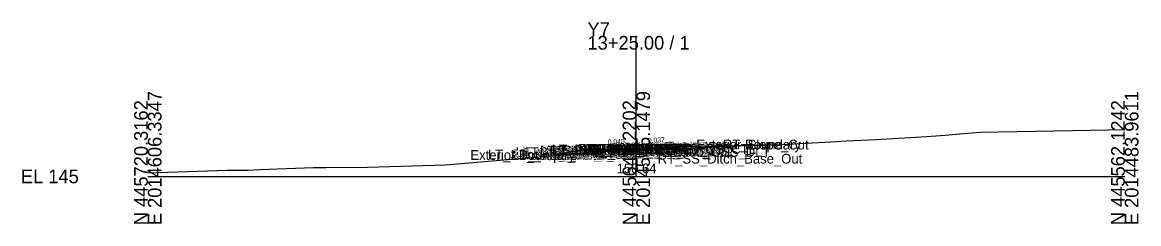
# Model space of a CAD drawing. Extents: x -26 to 203, y -10 to 7527.
# Drawn here: x -25.7 to 202.8, y 6490.3 to 6531.6 of the extents above; entities that cross this region are included whole.
import ezdxf

# ---------------------------------------------------------------- set-up
doc = ezdxf.new("R2010")
doc.units = 0
for name, color, linetype in [('Exist CMT Pavement', 7, 'Continuous'), ('Exist Cross Section Cell', 7, 'Continuous'), ('Exist XS Center Line Elevation Label', 7, 'Continuous'), ('Exist XS Ground Line', 7, 'Continuous'), ('Prop CMT Pvmt Course 1', 7, 'Continuous'), ('Prop CMT Pvmt Course 1 Wedge', 7, 'Continuous'), ('Prop CMT Pvmt Course 2', 7, 'Continuous'), ('Prop CMT Pvmt Course 2 Wedge', 7, 'Continuous'), ('Prop CMT Pvmt Course 3', 7, 'Continuous'), ('Prop CMT Pvmt Course 3 Wedge', 7, 'Continuous'), ('Prop CMT Pvmt Surface', 7, 'Continuous'), ('Prop CMT Pvmt Surface Shoulder', 7, 'Continuous'), ('Prop CMT Pvmt Wedge Surface 1', 7, 'Continuous'), ('Prop CMT Pvmt Wedge Surface 2', 7, 'Continuous'), ('Prop CMT Pvmt Wedge Surface 3', 7, 'Continuous'), ('Prop CMT Shld Paved Course 1', 7, 'Continuous'), ('Prop CMT Shld Paved Course 2', 7, 'Continuous'), ('Prop CMT Shld Paved Course 3', 7, 'Continuous'), ('Prop CMT Slope Grass', 7, 'Continuous'), ('Prop CMT Subgrade Earthwork', 7, 'Continuous'), ('Prop XS Earthwork Shape', 7, 'Continuous'), ('Prop XS SE Text', 7, 'Continuous'), ('Prop XS Side Slope Text', 7, 'Continuous'), ('Scratch_Level_0', 7, 'Continuous')]:
    doc.layers.add(name, color=color, linetype=linetype)

msp = doc.modelspace()

# ---------------------------------------------------------------- linework, layer by layer
at = {"layer": 'Exist CMT Pavement'}
msp.add_lwpolyline([(92.94, 6505.28), (96.94, 6505.54), (99.25, 6505.64), (100, 6505.64), (105.97, 6505.67), (107.36, 6505.68)], dxfattribs=at)
at = {"layer": 'Exist Cross Section Cell'}
for p, q in [((100, 6500), (100, 6528.78)), ((0, 6500), (100, 6500)), ((100, 6500), (200, 6500))]:
    msp.add_line(p, q, dxfattribs=at)
at = {"layer": 'Exist XS Ground Line'}
msp.add_lwpolyline([(0, 6500.76), (16.3, 6501.28), (20.4, 6501.31), (22.93, 6501.4), (33.83, 6501.79), (36.47, 6501.83), (44.97, 6501.9), (60.97, 6502.39), (87.21, 6504.6), (90.59, 6504.96), (90.9, 6505.08), (91.34, 6505.18), (96.94, 6505.54), (99.25, 6505.64), (100, 6505.64), (105.97, 6505.67), (108.19, 6505.68), (108.48, 6506.01), (108.95, 6505.67), (111.52, 6505.8), (120.48, 6506.25), (126.7, 6506.43), (127.61, 6506.46), (128.31, 6506.49), (134.74, 6506.84), (140.96, 6507.16), (141.87, 6507.2), (143.04, 6507.26), (149, 6507.57), (153.6, 6507.81), (156.13, 6507.96), (159.39, 6508.21), (163.25, 6508.45), (166.25, 6508.7), (170.38, 6509.08), (193.08, 6509.44), (200, 6509.59)], dxfattribs=at)
at = {"layer": 'Prop CMT Pvmt Course 1'}
for points in [[(100, 6505.79), (91.94, 6505.47)], [(91.94, 6505.47), (91.94, 6505.22)], [(91.94, 6505.22), (92.94, 6505.26)], [(92.94, 6505.39), (100, 6505.67)], [(92.94, 6505.26), (92.94, 6505.39)], [(100, 6505.79), (108.36, 6506.1)], [(107.36, 6505.94), (100, 6505.67)], [(100, 6505.54), (100, 6505.79)], [(100, 6505.54), (100, 6505.79)], [(100, 6505.67), (100, 6505.54), (100, 6505.54)], [(100, 6505.67), (100, 6505.54), (100, 6505.54)], [(107.36, 6505.82), (107.36, 6505.94)], [(108.36, 6505.85), (107.36, 6505.82)], [(108.36, 6506.1), (108.36, 6505.85)]]:
    msp.add_lwpolyline(points, dxfattribs=at)
at = {"layer": 'Prop CMT Pvmt Course 1 Wedge'}
for points in [[(100, 6505.67), (92.94, 6505.39)], [(100, 6505.67), (107.36, 6505.94)]]:
    msp.add_lwpolyline(points, dxfattribs=at)
at = {"layer": 'Prop CMT Pvmt Course 2'}
for points in [[(92.94, 6505.26), (91.94, 6505.22)], [(91.94, 6505.22), (91.94, 6504.97)], [(91.94, 6504.97), (92.94, 6505.01)], [(92.94, 6505.01), (92.94, 6505.26)], [(107.36, 6505.82), (108.36, 6505.85)], [(107.36, 6505.57), (107.36, 6505.82)], [(108.36, 6505.6), (107.36, 6505.57)], [(108.36, 6505.85), (108.36, 6505.6)]]:
    msp.add_lwpolyline(points, dxfattribs=at)
at = {"layer": 'Prop CMT Pvmt Course 2 Wedge'}
for points in [[(100, 6505.54), (92.94, 6505.26)], [(100, 6505.54), (107.36, 6505.82)]]:
    msp.add_lwpolyline(points, dxfattribs=at)
at = {"layer": 'Prop CMT Pvmt Course 3'}
for points in [[(92.94, 6505.01), (91.94, 6504.97)], [(91.94, 6504.97), (91.94, 6504.6)], [(91.94, 6504.6), (92.94, 6504.64)], [(92.94, 6504.64), (92.94, 6505.01)], [(107.36, 6505.57), (108.36, 6505.6)], [(107.36, 6505.19), (107.36, 6505.57)], [(108.36, 6505.23), (107.36, 6505.19)], [(108.36, 6505.6), (108.36, 6505.23)]]:
    msp.add_lwpolyline(points, dxfattribs=at)
at = {"layer": 'Prop CMT Pvmt Course 3 Wedge'}
for points in [[(100, 6505.29), (92.94, 6505.01)], [(100, 6505.29), (107.36, 6505.57)]]:
    msp.add_lwpolyline(points, dxfattribs=at)
at = {"layer": 'Prop CMT Pvmt Surface'}
for points in [[(100, 6505.79), (91.94, 6505.47)], [(100, 6505.79), (108.36, 6506.1)]]:
    msp.add_lwpolyline(points, dxfattribs=at)
at = {"layer": 'Prop CMT Pvmt Surface Shoulder'}
for points in [[(91.94, 6505.47), (91.94, 6505.47)], [(108.36, 6506.1), (108.36, 6506.1)]]:
    msp.add_lwpolyline(points, dxfattribs=at)
at = {"layer": 'Prop CMT Pvmt Wedge Surface 1'}
for points in [[(91.94, 6505.22), (91.94, 6505.47)], [(92.94, 6505.26), (91.94, 6505.22)], [(100, 6505.67), (92.94, 6505.39)], [(92.94, 6505.39), (92.94, 6505.26)], [(100, 6505.67), (107.36, 6505.94)], [(107.36, 6505.94), (107.36, 6505.82)], [(107.36, 6505.82), (108.36, 6505.85)], [(108.36, 6505.85), (108.36, 6506.1)]]:
    msp.add_lwpolyline(points, dxfattribs=at)
at = {"layer": 'Prop CMT Pvmt Wedge Surface 2'}
for points in [[(100, 6505.54), (91.94, 6505.22)], [(91.94, 6505.22), (91.94, 6505.47)], [(100, 6505.54), (108.36, 6505.85)], [(108.36, 6505.85), (108.36, 6506.1)]]:
    msp.add_lwpolyline(points, dxfattribs=at)
at = {"layer": 'Prop CMT Pvmt Wedge Surface 3'}
for points in [[(91.94, 6504.97), (91.94, 6505.47)], [(100, 6505.29), (91.94, 6504.97)], [(100, 6505.29), (108.36, 6505.6)], [(108.36, 6505.6), (108.36, 6506.1)]]:
    msp.add_lwpolyline(points, dxfattribs=at)
at = {"layer": 'Prop CMT Shld Paved Course 1'}
for points in [[(91.94, 6505.47), (91.69, 6505.22)], [(91.69, 6505.22), (91.94, 6505.22)], [(91.94, 6505.47), (91.94, 6505.47)], [(91.94, 6505.22), (91.94, 6505.47)], [(108.36, 6506.1), (108.36, 6506.1)], [(108.36, 6506.1), (108.62, 6505.85)], [(108.36, 6505.85), (108.36, 6506.1)], [(108.62, 6505.85), (108.36, 6505.85)]]:
    msp.add_lwpolyline(points, dxfattribs=at)
at = {"layer": 'Prop CMT Shld Paved Course 2'}
for points in [[(91.94, 6505.22), (91.69, 6505.22), (91.43, 6504.96)], [(91.43, 6504.96), (91.94, 6504.97)], [(91.94, 6504.97), (91.94, 6505.22)], [(108.36, 6505.85), (108.62, 6505.85), (108.87, 6505.59)], [(108.36, 6505.6), (108.36, 6505.85)], [(108.87, 6505.59), (108.36, 6505.6)]]:
    msp.add_lwpolyline(points, dxfattribs=at)
at = {"layer": 'Prop CMT Shld Paved Course 3'}
for points in [[(90.55, 6504.57), (91.94, 6504.6)], [(91.94, 6504.97), (91.43, 6504.96), (91.05, 6504.58)], [(91.94, 6504.6), (91.94, 6504.97)], [(108.36, 6505.23), (108.36, 6505.6)], [(108.36, 6505.6), (108.87, 6505.59), (109.26, 6505.21)], [(109.76, 6505.2), (108.36, 6505.23)]]:
    msp.add_lwpolyline(points, dxfattribs=at)
at = {"layer": 'Prop CMT Slope Grass'}
for points in [[(108.36, 6506.1), (128.07, 6506.48)], [(91.94, 6505.47), (85.94, 6504.99), (83.93, 6504.32)]]:
    msp.add_lwpolyline(points, dxfattribs=at)
at = {"layer": 'Prop CMT Subgrade Earthwork'}
msp.add_line((109.76, 6505.2), (113.05, 6506.19), dxfattribs=at)
for points in [[(90.55, 6504.57), (84.49, 6504.51)], [(91.94, 6504.6), (90.55, 6504.57)], [(92.94, 6504.64), (91.94, 6504.6)], [(92.94, 6504.64), (92.94, 6505.28)], [(107.36, 6505.19), (107.36, 6505.68)], [(107.36, 6505.19), (108.36, 6505.23)], [(108.36, 6505.23), (109.76, 6505.2)]]:
    msp.add_lwpolyline(points, dxfattribs=at)
at = {"layer": 'Prop XS Earthwork Shape'}
for points in [[(111.78, 6505.81), (113.05, 6506.19), (128.07, 6506.48), (120.48, 6506.25)], [(83.93, 6504.32), (86.37, 6504.52), (84.49, 6504.51)], [(91.34, 6505.18), (92.94, 6505.28), (92.94, 6504.64), (91.94, 6504.6), (90.55, 6504.57), (86.37, 6504.52), (87.21, 6504.6), (90.59, 6504.96), (90.9, 6505.08)], [(108.48, 6506.01), (108.95, 6505.67), (111.52, 6505.8), (111.78, 6505.81), (109.76, 6505.2), (108.36, 6505.23), (107.36, 6505.19), (107.36, 6505.68), (108.19, 6505.68)]]:
    msp.add_lwpolyline(points, close=True, dxfattribs=at)

# ---------------------------------------------------------------- texts
at = {"layer": 'Exist Cross Section Cell'}
for s, p in [('Y7', (90, 6528.78)), ('13+25.00 / 1', (90, 6525.98)), ('EL 145', (-26, 6498.6))]:
    msp.add_text(s, height=2.8, dxfattribs=at).set_placement(p)
for s, p in [('E 2014606.3347', (2.8, 6490)), ('E 2014545.1479', (102.8, 6490)), ('E 2014483.9611', (202.8, 6490)), ('N 445720.3162', (0, 6490)), ('N 445641.2202', (100, 6490)), ('N 445562.1242', (200, 6490))]:
    msp.add_text(s, height=2.8, rotation=90, dxfattribs=at).set_placement(p)
at = {"layer": 'Exist XS Center Line Elevation Label'}
msp.add_text('150.64', height=2, dxfattribs=at).set_placement((95.96, 6500.64))
at = {"layer": 'Prop XS SE Text'}
for s, rotation, p in [('0.040', 2.2906, (94.18, 6506.56)), ('0.037', 2.134, (102.39, 6506.88))]:
    msp.add_text(s, height=1, rotation=rotation, dxfattribs=at).set_placement(p)
at = {"layer": 'Prop XS Side Slope Text'}
msp.add_text('3:1', height=1, rotation=18.4333, dxfattribs=at).set_placement((83.98, 6505.13))
at = {"layer": 'Scratch_Level_0'}
for s, p in [('LT_Sub Tie Out', (80.28, 6504.28)), ('LT_PV1_OEOT', (82.68, 6504.47)), ('LT_PS1_OEOP', (82.75, 6504.47)), ('LT_PV1_OEEOP', (82.82, 6504.39)), ('RT_PV_IEEOP_EG', (88.14, 6504.64)), ('LT_PV_IEEOP_EG', (88.19, 6504.64)), ('RT_PV2_IEEOP', (89.91, 6504.54)), ('LT_PV2_IEEOP', (89.95, 6504.54)), ('RT_PV1_IEEOP', (90.47, 6504.67)), ('LT_PV1_IEEOP', (90.52, 6504.67)), ('PV2_PGL', (93.91, 6504.54)), ('PV1_PGL', (94.47, 6504.79)), ('RT_Sub Tie Out', (94.65, 6504.69)), ('RT_PV_OEEOP_EG', (94.86, 6504.69)), ('RT_PS3_Shelf_Out', (95.31, 6504.58)), ('RT_PV2_OEEOP', (96.62, 6504.82)), ('RT_PV3_OEEOP', (96.62, 6504.57)), ('RT_PV1_OEEOP', (97.19, 6504.94)), ('RT_Sub_OEOT', (98.39, 6504.23)), ('RT_PV2_OEOT', (98.49, 6504.85)), ('RT_PV3_OEOT', (98.49, 6504.6)), ('RT_PS2_OEOP', (98.81, 6504.85)), ('RT_PV1_OEOT', (99.06, 6505.1)), ('RT_PS3_OEOP', (99.06, 6504.59)), ('RT_PS1_OEOP', (99.12, 6505.1)), ('RT_GS_OS_CTL', (103.68, 6504.62)), ('Exterior Boundary', (112.29, 6505.52)), ('RT_Slope_Cut', (117.74, 6505.52)), ('Exterior Boundary', (66.04, 6503.38)), ('LT_Sub_OSS_DLT', (69.62, 6503.48)), ('LT_Slope_Fill', (74.51, 6503.34)), ('LT_Sub_Trench_Out', (74.76, 6503.57)), ('LT_GS_OS_CTL', (75.31, 6503.99)), ('LT_PS3_Shelf_Out', (76.92, 6503.95)), ('LT_PV_OEEOP_EG', (80.49, 6504.28)), ('LT_PS3_OEOP', (81.67, 6503.96)), ('LT_PS2_OEOP', (81.93, 6504.22)), ('LT_Sub_OEOT', (82.02, 6503.6)), ('LT_PV2_OEOT', (82.12, 6504.22)), ('LT_PV3_OEOT', (82.12, 6503.97)), ('LT_Sub_OEEOP', (82.16, 6503.64)), ('LT_PV2_OEEOP', (82.25, 6504.26)), ('LT_PV3_OEEOP', (82.25, 6504.01)), ('RT_PV3_IEEOP', (89.91, 6504.29)), ('LT_PV3_IEEOP', (89.95, 6504.29)), ('RT_Sub_Trench_Out', (93.91, 6504.2)), ('RT_Sub_OEEOP', (96.53, 6504.19)), ('RT_Sub_OSS_DLT', (103.96, 6504.06)), ('RT_SS_Ditch_Base_Out', (104.39, 6502.62))]:
    msp.add_text(s, height=2, dxfattribs=at).set_placement(p)

doc.saveas('drawing.dxf')
